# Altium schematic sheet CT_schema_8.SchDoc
size 259 x 245 mm
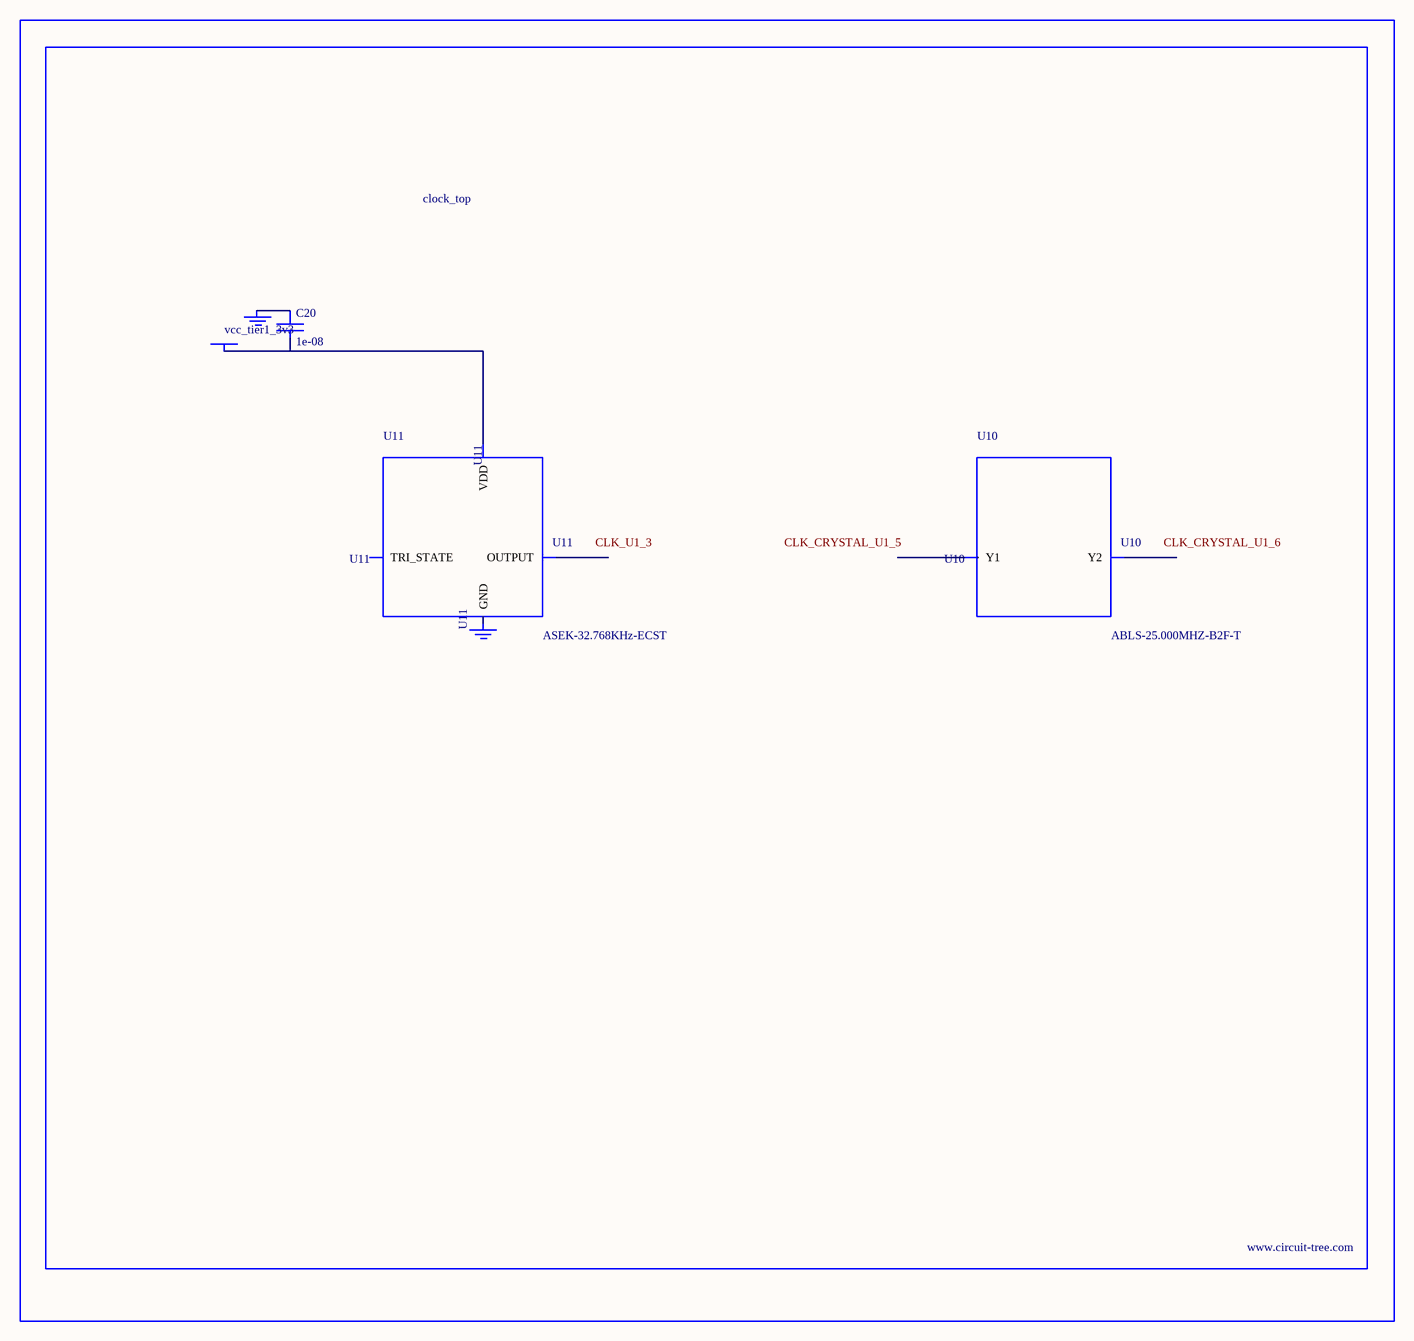
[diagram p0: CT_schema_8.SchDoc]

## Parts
BORDER7  (no value)
C20  1e-08  [C0402]
GND_INSTANCE_7_0  (no value)
GND_INSTANCE_7_1  (no value)
POWER_INSTANCE_7_0  vcc_tier1_3v3
U10  ABLS-25.000MHZ-B2F-T  [ABLS-25.000MHZ-B2F-T]
U11  ASEK-32.768KHz-ECST  [ASEK]

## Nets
NetC20_1: C20.1 GND_INSTANCE_7_0.0(GND)
NetC20_2: C20.2 POWER_INSTANCE_7_0.0(PWR) U11.4(VDD)

Not connected (* = marked no-connect by the designer): GND_INSTANCE_7_1 0(GND); U10 1(Y1) 2(Y2); U11 1(TRI_STATE) 2(GND) 3(OUTPUT)

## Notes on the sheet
- Labels drawn without touching a wire or pin: CLK_CRYSTAL_U1_5, CLK_CRYSTAL_U1_6, CLK_U1_3

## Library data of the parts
BORDER7 = BORDER_PAGE7
C20 = C0402C103K3RAC
GND_INSTANCE_7_0 GND_INSTANCE_7_1 = GND
POWER_INSTANCE_7_0 = PWR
